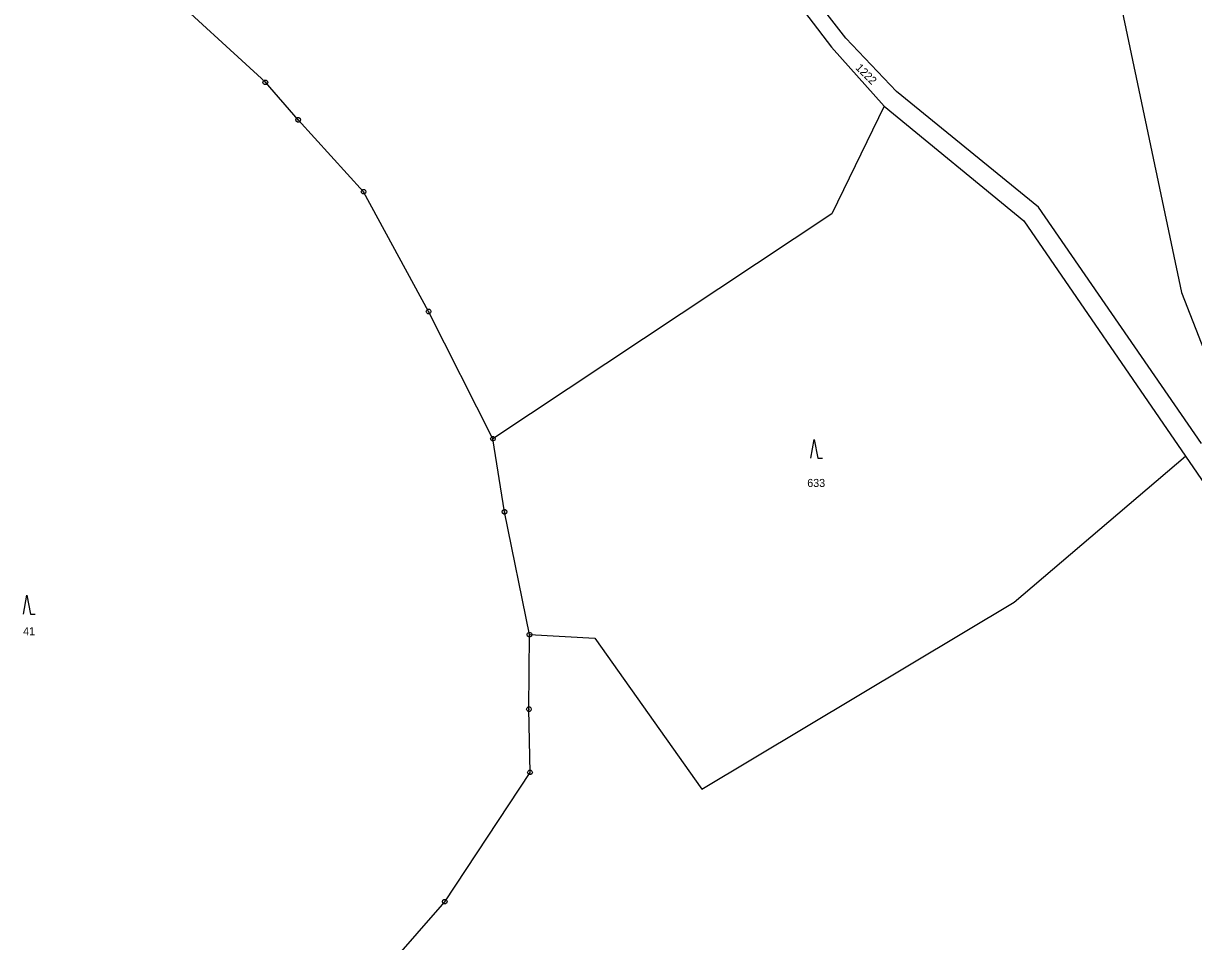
# Model space of a CAD drawing. Extents: x -694465 to -690527, y -983694 to -978978.
# Drawn here: x -692129.9 to -691881.4, y -979641 to -979445.8 of the extents above; entities that cross this region are included whole.
import ezdxf

# ---------------------------------------------------------------- set-up
doc = ezdxf.new("R2010")
doc.units = 0
for name, color, linetype in [('Vrstva 1', 7, 'Continuous'), ('Vrstva 18', 7, 'Continuous'), ('Vrstva 24', 7, 'Continuous'), ('Vrstva 25', 7, 'Continuous')]:
    doc.layers.add(name, color=color, linetype=linetype)

msp = doc.modelspace()

# ---------------------------------------------------------------- linework, layer by layer
at = {"layer": 'Vrstva 1'}
for points in [[(-691896.74, -979376.32), (-691899.3, -979430.06), (-691883.9, -979503.03), (-691874.32, -979527.65), (-691872.34, -979530.22)], [(-691955.22, -979448.95), (-691968.3, -979432.07)], [(-691970.88, -979434.29), (-691958.27, -979450.85)], [(-692078.53, -979458.35), (-692101.11, -979437.56)], [(-691958.27, -979450.85), (-691947.08, -979463.4)], [(-691944.49, -979460.3), (-691955.22, -979448.95)], [(-692071.55, -979466.32), (-692078.53, -979458.35)], [(-691914.26, -979484.9), (-691944.49, -979460.3)], [(-691947.08, -979463.4), (-691958.23, -979486.28)], [(-691947.08, -979463.4), (-691917.4, -979487.76)], [(-692057.65, -979481.61), (-692071.55, -979466.32)], [(-692043.84, -979507.06), (-692057.65, -979481.61)], [(-691879.66, -979535.13), (-691914.26, -979484.9)], [(-691958.23, -979486.28), (-692030.19, -979534.11)], [(-691917.4, -979487.76), (-691883.04, -979537.83)], [(-692030.19, -979534.11), (-692043.84, -979507.06)], [(-692027.74, -979549.64), (-692030.19, -979534.11)], [(-691919.44, -979568.85), (-691883.04, -979537.83)], [(-691883.04, -979537.83), (-691853.5, -979580.98)], [(-692022.41, -979575.75), (-692027.74, -979549.64)], [(-691985.84, -979608.56), (-691919.44, -979568.85)], [(-692022.53, -979591.59), (-692022.41, -979575.75)], [(-692022.41, -979575.75), (-692008.57, -979576.49)], [(-692008.57, -979576.49), (-691985.84, -979608.56)], [(-692022.31, -979605.03), (-692022.53, -979591.59)], [(-692040.43, -979632.5), (-692022.31, -979605.03)], [(-692068.76, -979665.02), (-692040.43, -979632.5)]]:
    msp.add_lwpolyline(points, dxfattribs=at)
at = {"layer": 'Vrstva 24'}
for points in [[(-692078.376, -979457.874), (-692078.126, -979458.056), (-692078.03, -979458.35), (-692078.126, -979458.644), (-692078.376, -979458.826), (-692078.684, -979458.826), (-692078.934, -979458.644), (-692079.03, -979458.35), (-692078.934, -979458.056), (-692078.684, -979457.874)], [(-692078.376, -979457.874), (-692078.126, -979458.056), (-692078.03, -979458.35), (-692078.126, -979458.644), (-692078.376, -979458.826), (-692078.684, -979458.826), (-692078.934, -979458.644), (-692079.03, -979458.35), (-692078.934, -979458.056), (-692078.684, -979457.874)], [(-692078.376, -979457.874), (-692078.126, -979458.056), (-692078.03, -979458.35), (-692078.126, -979458.644), (-692078.376, -979458.826), (-692078.684, -979458.826), (-692078.934, -979458.644), (-692079.03, -979458.35), (-692078.934, -979458.056), (-692078.684, -979457.874)], [(-692078.376, -979457.874), (-692078.126, -979458.056), (-692078.03, -979458.35), (-692078.126, -979458.644), (-692078.376, -979458.826), (-692078.684, -979458.826), (-692078.934, -979458.644), (-692079.03, -979458.35), (-692078.934, -979458.056), (-692078.684, -979457.874)], [(-692071.396, -979465.844), (-692071.146, -979466.026), (-692071.05, -979466.32), (-692071.146, -979466.614), (-692071.396, -979466.796), (-692071.704, -979466.796), (-692071.954, -979466.614), (-692072.05, -979466.32), (-692071.954, -979466.026), (-692071.704, -979465.844)], [(-692071.396, -979465.844), (-692071.146, -979466.026), (-692071.05, -979466.32), (-692071.146, -979466.614), (-692071.396, -979466.796), (-692071.704, -979466.796), (-692071.954, -979466.614), (-692072.05, -979466.32), (-692071.954, -979466.026), (-692071.704, -979465.844)], [(-692071.396, -979465.844), (-692071.146, -979466.026), (-692071.05, -979466.32), (-692071.146, -979466.614), (-692071.396, -979466.796), (-692071.704, -979466.796), (-692071.954, -979466.614), (-692072.05, -979466.32), (-692071.954, -979466.026), (-692071.704, -979465.844)], [(-692071.396, -979465.844), (-692071.146, -979466.026), (-692071.05, -979466.32), (-692071.146, -979466.614), (-692071.396, -979466.796), (-692071.704, -979466.796), (-692071.954, -979466.614), (-692072.05, -979466.32), (-692071.954, -979466.026), (-692071.704, -979465.844)], [(-692057.496, -979481.134), (-692057.246, -979481.316), (-692057.15, -979481.61), (-692057.246, -979481.904), (-692057.496, -979482.086), (-692057.804, -979482.086), (-692058.054, -979481.904), (-692058.15, -979481.61), (-692058.054, -979481.316), (-692057.804, -979481.134)], [(-692057.496, -979481.134), (-692057.246, -979481.316), (-692057.15, -979481.61), (-692057.246, -979481.904), (-692057.496, -979482.086), (-692057.804, -979482.086), (-692058.054, -979481.904), (-692058.15, -979481.61), (-692058.054, -979481.316), (-692057.804, -979481.134)], [(-692057.496, -979481.134), (-692057.246, -979481.316), (-692057.15, -979481.61), (-692057.246, -979481.904), (-692057.496, -979482.086), (-692057.804, -979482.086), (-692058.054, -979481.904), (-692058.15, -979481.61), (-692058.054, -979481.316), (-692057.804, -979481.134)], [(-692057.496, -979481.134), (-692057.246, -979481.316), (-692057.15, -979481.61), (-692057.246, -979481.904), (-692057.496, -979482.086), (-692057.804, -979482.086), (-692058.054, -979481.904), (-692058.15, -979481.61), (-692058.054, -979481.316), (-692057.804, -979481.134)], [(-692043.686, -979506.584), (-692043.436, -979506.766), (-692043.34, -979507.06), (-692043.436, -979507.354), (-692043.686, -979507.536), (-692043.994, -979507.536), (-692044.244, -979507.354), (-692044.34, -979507.06), (-692044.244, -979506.766), (-692043.994, -979506.584)], [(-692043.686, -979506.584), (-692043.436, -979506.766), (-692043.34, -979507.06), (-692043.436, -979507.354), (-692043.686, -979507.536), (-692043.994, -979507.536), (-692044.244, -979507.354), (-692044.34, -979507.06), (-692044.244, -979506.766), (-692043.994, -979506.584)], [(-692043.686, -979506.584), (-692043.436, -979506.766), (-692043.34, -979507.06), (-692043.436, -979507.354), (-692043.686, -979507.536), (-692043.994, -979507.536), (-692044.244, -979507.354), (-692044.34, -979507.06), (-692044.244, -979506.766), (-692043.994, -979506.584)], [(-692043.686, -979506.584), (-692043.436, -979506.766), (-692043.34, -979507.06), (-692043.436, -979507.354), (-692043.686, -979507.536), (-692043.994, -979507.536), (-692044.244, -979507.354), (-692044.34, -979507.06), (-692044.244, -979506.766), (-692043.994, -979506.584)], [(-692030.036, -979533.634), (-692029.786, -979533.816), (-692029.69, -979534.11), (-692029.786, -979534.404), (-692030.036, -979534.586), (-692030.344, -979534.586), (-692030.594, -979534.404), (-692030.69, -979534.11), (-692030.594, -979533.816), (-692030.344, -979533.634)], [(-692030.036, -979533.634), (-692029.786, -979533.816), (-692029.69, -979534.11), (-692029.786, -979534.404), (-692030.036, -979534.586), (-692030.344, -979534.586), (-692030.594, -979534.404), (-692030.69, -979534.11), (-692030.594, -979533.816), (-692030.344, -979533.634)], [(-692030.036, -979533.634), (-692029.786, -979533.816), (-692029.69, -979534.11), (-692029.786, -979534.404), (-692030.036, -979534.586), (-692030.344, -979534.586), (-692030.594, -979534.404), (-692030.69, -979534.11), (-692030.594, -979533.816), (-692030.344, -979533.634)], [(-692030.036, -979533.634), (-692029.786, -979533.816), (-692029.69, -979534.11), (-692029.786, -979534.404), (-692030.036, -979534.586), (-692030.344, -979534.586), (-692030.594, -979534.404), (-692030.69, -979534.11), (-692030.594, -979533.816), (-692030.344, -979533.634)], [(-692027.586, -979549.164), (-692027.336, -979549.346), (-692027.24, -979549.64), (-692027.336, -979549.934), (-692027.586, -979550.116), (-692027.894, -979550.116), (-692028.144, -979549.934), (-692028.24, -979549.64), (-692028.144, -979549.346), (-692027.894, -979549.164)], [(-692027.586, -979549.164), (-692027.336, -979549.346), (-692027.24, -979549.64), (-692027.336, -979549.934), (-692027.586, -979550.116), (-692027.894, -979550.116), (-692028.144, -979549.934), (-692028.24, -979549.64), (-692028.144, -979549.346), (-692027.894, -979549.164)], [(-692027.586, -979549.164), (-692027.336, -979549.346), (-692027.24, -979549.64), (-692027.336, -979549.934), (-692027.586, -979550.116), (-692027.894, -979550.116), (-692028.144, -979549.934), (-692028.24, -979549.64), (-692028.144, -979549.346), (-692027.894, -979549.164)], [(-692027.586, -979549.164), (-692027.336, -979549.346), (-692027.24, -979549.64), (-692027.336, -979549.934), (-692027.586, -979550.116), (-692027.894, -979550.116), (-692028.144, -979549.934), (-692028.24, -979549.64), (-692028.144, -979549.346), (-692027.894, -979549.164)], [(-692022.256, -979575.274), (-692022.006, -979575.456), (-692021.91, -979575.75), (-692022.006, -979576.044), (-692022.256, -979576.226), (-692022.564, -979576.226), (-692022.814, -979576.044), (-692022.91, -979575.75), (-692022.814, -979575.456), (-692022.564, -979575.274)], [(-692022.256, -979575.274), (-692022.006, -979575.456), (-692021.91, -979575.75), (-692022.006, -979576.044), (-692022.256, -979576.226), (-692022.564, -979576.226), (-692022.814, -979576.044), (-692022.91, -979575.75), (-692022.814, -979575.456), (-692022.564, -979575.274)], [(-692022.256, -979575.274), (-692022.006, -979575.456), (-692021.91, -979575.75), (-692022.006, -979576.044), (-692022.256, -979576.226), (-692022.564, -979576.226), (-692022.814, -979576.044), (-692022.91, -979575.75), (-692022.814, -979575.456), (-692022.564, -979575.274)], [(-692022.256, -979575.274), (-692022.006, -979575.456), (-692021.91, -979575.75), (-692022.006, -979576.044), (-692022.256, -979576.226), (-692022.564, -979576.226), (-692022.814, -979576.044), (-692022.91, -979575.75), (-692022.814, -979575.456), (-692022.564, -979575.274)], [(-692022.376, -979591.114), (-692022.126, -979591.296), (-692022.03, -979591.59), (-692022.126, -979591.884), (-692022.376, -979592.066), (-692022.684, -979592.066), (-692022.934, -979591.884), (-692023.03, -979591.59), (-692022.934, -979591.296), (-692022.684, -979591.114)], [(-692022.376, -979591.114), (-692022.126, -979591.296), (-692022.03, -979591.59), (-692022.126, -979591.884), (-692022.376, -979592.066), (-692022.684, -979592.066), (-692022.934, -979591.884), (-692023.03, -979591.59), (-692022.934, -979591.296), (-692022.684, -979591.114)], [(-692022.376, -979591.114), (-692022.126, -979591.296), (-692022.03, -979591.59), (-692022.126, -979591.884), (-692022.376, -979592.066), (-692022.684, -979592.066), (-692022.934, -979591.884), (-692023.03, -979591.59), (-692022.934, -979591.296), (-692022.684, -979591.114)], [(-692022.376, -979591.114), (-692022.126, -979591.296), (-692022.03, -979591.59), (-692022.126, -979591.884), (-692022.376, -979592.066), (-692022.684, -979592.066), (-692022.934, -979591.884), (-692023.03, -979591.59), (-692022.934, -979591.296), (-692022.684, -979591.114)], [(-692022.376, -979591.114), (-692022.126, -979591.296), (-692022.03, -979591.59), (-692022.126, -979591.884), (-692022.376, -979592.066), (-692022.684, -979592.066), (-692022.934, -979591.884), (-692023.03, -979591.59), (-692022.934, -979591.296), (-692022.684, -979591.114)], [(-692022.376, -979591.114), (-692022.126, -979591.296), (-692022.03, -979591.59), (-692022.126, -979591.884), (-692022.376, -979592.066), (-692022.684, -979592.066), (-692022.934, -979591.884), (-692023.03, -979591.59), (-692022.934, -979591.296), (-692022.684, -979591.114)], [(-692022.156, -979604.554), (-692021.906, -979604.736), (-692021.81, -979605.03), (-692021.906, -979605.324), (-692022.156, -979605.506), (-692022.464, -979605.506), (-692022.714, -979605.324), (-692022.81, -979605.03), (-692022.714, -979604.736), (-692022.464, -979604.554)], [(-692022.156, -979604.554), (-692021.906, -979604.736), (-692021.81, -979605.03), (-692021.906, -979605.324), (-692022.156, -979605.506), (-692022.464, -979605.506), (-692022.714, -979605.324), (-692022.81, -979605.03), (-692022.714, -979604.736), (-692022.464, -979604.554)], [(-692022.156, -979604.554), (-692021.906, -979604.736), (-692021.81, -979605.03), (-692021.906, -979605.324), (-692022.156, -979605.506), (-692022.464, -979605.506), (-692022.714, -979605.324), (-692022.81, -979605.03), (-692022.714, -979604.736), (-692022.464, -979604.554)], [(-692022.156, -979604.554), (-692021.906, -979604.736), (-692021.81, -979605.03), (-692021.906, -979605.324), (-692022.156, -979605.506), (-692022.464, -979605.506), (-692022.714, -979605.324), (-692022.81, -979605.03), (-692022.714, -979604.736), (-692022.464, -979604.554)], [(-692022.156, -979604.554), (-692021.906, -979604.736), (-692021.81, -979605.03), (-692021.906, -979605.324), (-692022.156, -979605.506), (-692022.464, -979605.506), (-692022.714, -979605.324), (-692022.81, -979605.03), (-692022.714, -979604.736), (-692022.464, -979604.554)], [(-692022.156, -979604.554), (-692021.906, -979604.736), (-692021.81, -979605.03), (-692021.906, -979605.324), (-692022.156, -979605.506), (-692022.464, -979605.506), (-692022.714, -979605.324), (-692022.81, -979605.03), (-692022.714, -979604.736), (-692022.464, -979604.554)], [(-692040.276, -979632.024), (-692040.026, -979632.206), (-692039.93, -979632.5), (-692040.026, -979632.794), (-692040.276, -979632.976), (-692040.584, -979632.976), (-692040.834, -979632.794), (-692040.93, -979632.5), (-692040.834, -979632.206), (-692040.584, -979632.024)], [(-692040.276, -979632.024), (-692040.026, -979632.206), (-692039.93, -979632.5), (-692040.026, -979632.794), (-692040.276, -979632.976), (-692040.584, -979632.976), (-692040.834, -979632.794), (-692040.93, -979632.5), (-692040.834, -979632.206), (-692040.584, -979632.024)], [(-692040.276, -979632.024), (-692040.026, -979632.206), (-692039.93, -979632.5), (-692040.026, -979632.794), (-692040.276, -979632.976), (-692040.584, -979632.976), (-692040.834, -979632.794), (-692040.93, -979632.5), (-692040.834, -979632.206), (-692040.584, -979632.024)], [(-692040.276, -979632.024), (-692040.026, -979632.206), (-692039.93, -979632.5), (-692040.026, -979632.794), (-692040.276, -979632.976), (-692040.584, -979632.976), (-692040.834, -979632.794), (-692040.93, -979632.5), (-692040.834, -979632.206), (-692040.584, -979632.024)]]:
    msp.add_lwpolyline(points, close=True, dxfattribs=at)
for points in [[(-692078.649, -979458.35), (-692078.41, -979458.35)], [(-692078.649, -979458.35), (-692078.41, -979458.35)], [(-692078.649, -979458.35), (-692078.41, -979458.35)], [(-692078.649, -979458.35), (-692078.41, -979458.35)], [(-692071.669, -979466.32), (-692071.43, -979466.32)], [(-692071.669, -979466.32), (-692071.43, -979466.32)], [(-692071.669, -979466.32), (-692071.43, -979466.32)], [(-692071.669, -979466.32), (-692071.43, -979466.32)], [(-692057.769, -979481.61), (-692057.53, -979481.61)], [(-692057.769, -979481.61), (-692057.53, -979481.61)], [(-692057.769, -979481.61), (-692057.53, -979481.61)], [(-692057.769, -979481.61), (-692057.53, -979481.61)], [(-692043.959, -979507.06), (-692043.72, -979507.06)], [(-692043.959, -979507.06), (-692043.72, -979507.06)], [(-692043.959, -979507.06), (-692043.72, -979507.06)], [(-692043.959, -979507.06), (-692043.72, -979507.06)], [(-692030.309, -979534.11), (-692030.07, -979534.11)], [(-692030.309, -979534.11), (-692030.07, -979534.11)], [(-692030.309, -979534.11), (-692030.07, -979534.11)], [(-692030.309, -979534.11), (-692030.07, -979534.11)], [(-692027.859, -979549.64), (-692027.62, -979549.64)], [(-692027.859, -979549.64), (-692027.62, -979549.64)], [(-692027.859, -979549.64), (-692027.62, -979549.64)], [(-692027.859, -979549.64), (-692027.62, -979549.64)], [(-692022.529, -979575.75), (-692022.29, -979575.75)], [(-692022.529, -979575.75), (-692022.29, -979575.75)], [(-692022.529, -979575.75), (-692022.29, -979575.75)], [(-692022.529, -979575.75), (-692022.29, -979575.75)], [(-692022.649, -979591.59), (-692022.41, -979591.59)], [(-692022.649, -979591.59), (-692022.41, -979591.59)], [(-692022.649, -979591.59), (-692022.41, -979591.59)], [(-692022.649, -979591.59), (-692022.41, -979591.59)], [(-692022.649, -979591.59), (-692022.41, -979591.59)], [(-692022.649, -979591.59), (-692022.41, -979591.59)], [(-692022.429, -979605.03), (-692022.19, -979605.03)], [(-692022.429, -979605.03), (-692022.19, -979605.03)], [(-692022.429, -979605.03), (-692022.19, -979605.03)], [(-692022.429, -979605.03), (-692022.19, -979605.03)], [(-692022.429, -979605.03), (-692022.19, -979605.03)], [(-692022.429, -979605.03), (-692022.19, -979605.03)], [(-692040.549, -979632.5), (-692040.31, -979632.5)], [(-692040.549, -979632.5), (-692040.31, -979632.5)], [(-692040.549, -979632.5), (-692040.31, -979632.5)], [(-692040.549, -979632.5), (-692040.31, -979632.5)]]:
    msp.add_lwpolyline(points, dxfattribs=at)
at = {"layer": 'Vrstva 25'}
for points in [[(-691962.69, -979538.24), (-691961.94, -979534.24), (-691961.19, -979538.24), (-691960.19, -979538.24)], [(-692129.92, -979571.36), (-692129.17, -979567.36), (-692128.42, -979571.36), (-692127.42, -979571.36)]]:
    msp.add_lwpolyline(points, dxfattribs=at)

# ---------------------------------------------------------------- texts
at = {"layer": 'Vrstva 18'}
msp.add_text('1222', height=1.7, rotation=315.01219, dxfattribs=at).set_placement((-691953.26, -979455.401))
for s, p in [('633', (-691963.413, -979544.35)), ('41', (-692129.973, -979575.86))]:
    msp.add_text(s, height=1.7, dxfattribs=at).set_placement(p)

doc.saveas('drawing.dxf')
